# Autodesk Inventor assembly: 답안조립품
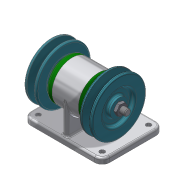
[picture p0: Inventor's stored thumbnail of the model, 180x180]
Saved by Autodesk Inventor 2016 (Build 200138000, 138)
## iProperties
Created: 2019-09
Part Number: 답안조립품
Material: 일반
Document SubType Name: Assembly
Designer: Administrator
Author: Administrator
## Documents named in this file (10)
- C:\Users\Administrator\Desktop\490904v1046\답안조립품.iam
- C:\Users\Administrator\Desktop\490904v1046\본체.ipt
- C:\Users\Administrator\Desktop\490904v1046\베어링 6004.ipt
- C:\Users\Administrator\Desktop\490904v1046\축.ipt
- C:\Users\Administrator\Desktop\490904v1046\오일 실 17 30 5.ipt
- C:\Users\Administrator\Desktop\490904v1046\커버.ipt
- C:\Users\Administrator\Desktop\490904v1046\볼트 M4.ipt
- C:\Users\Administrator\Desktop\490904v1046\V-벨트풀리.ipt
- C:\Users\Administrator\Desktop\490904v1046\너트 M10x1.ipt
- C:\Users\Administrator\Desktop\490904v1046\키 5 x 5 x 12.ipt
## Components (2 placed, 1 different names)
1. V-벨트풀리:1 — 각도:2
2. V-벨트풀리:2 — 각도:1
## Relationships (2: Angle 2)
- 각도:1 [Angle]: V-벨트풀리:2
- 각도:2 [Angle]: V-벨트풀리:1
